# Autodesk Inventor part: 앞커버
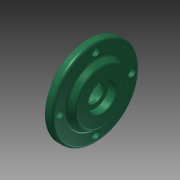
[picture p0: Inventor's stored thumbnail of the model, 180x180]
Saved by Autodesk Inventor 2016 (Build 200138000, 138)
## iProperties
Created: 2015-11
Part Number: 앞커버
Material: 알루미늄 6061
Document SubType Name: Modeling
Designer: mduedu
Density: 2.71 g/cm^3
Appearance: 매끄러움 - 짙은 바다 녹색
Mass: 245.264 g
Surface Area: 216.158 cm^2
Volume: 90.5034 cm^3
Author: mduedu
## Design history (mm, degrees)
sketch "스케치1"
  geometry: C1 r 47.5 at (0, 0); 1 further point
  constraints: 1 centre point, 1 coincident
  dimensions: "d57" = 95 diameter of C1
extrude "돌출1" new body sketch "스케치1" distance "d3" = 8; taper "d4" = 0 deg
sketch "스케치2"
  geometry: C1 r 32.5 at (0, 0); 1 further point
  constraints: 1 centre point, 1 coincident
  dimensions: "d5" = 65 diameter of C1
extrude "돌출2" join sketch "스케치2" distance "d6" = 7; taper "d7" = -30 deg
sketch "스케치3" dims "d58" = 78
  geometry: 3 further points
  constraints: 2 vertical alignment, 1 coincident, 2 other
hole "구멍1" sketch "스케치3" at (0, 39) diameter "d11" = 4.5; stored, may be unused: countersink angle "d15" = 90 deg, drill point angle "d17" = 118 deg; dims "d12" = 6, "d13" = 8, "d14" = 4.4, "d16" = 8
sketch "스케치4"
  geometry: C1 r 32.5 at (0, 0); 1 further point
  constraints: 1 centre point, 1 coincident
  dimensions: "d21" = 65 diameter of C1
extrude "돌출3" join sketch "스케치4" distance "d23" = 12; taper "d24" = 0 deg
hole "구멍2" diameter "d27" = 34; stored, may be unused: countersink angle "d31" = 90 deg, drill point angle "d33" = 0 deg; dims "d28" = 6, "d29" = 40, "d30" = 12, "d32" = 15, "d65" = 10, "d66" = 10
fillet "모깎기3" dims "d36" = 3
fillet "모깎기4" dims "d37" = 3
fillet "모깎기5" dims "d38" = 0.3
chamfer "모따기1" distance "d39" = 1; stored, may be unused: second distance "d40" = 2, angle "d41" = 45 deg
hole "구멍3" diameter "d44" = 20; stored, may be unused: countersink angle "d48" = 90 deg, drill point angle "d50" = 118 deg; dims "d45" = 6, "d46" = 30, "d47" = 8.3, "d49" = 8, "d59" = 10, "d60" = 10
fillet "모깎기6" dims "d51" = 0.3
chamfer "모따기2" distance "d52" = 0.8; stored, may be unused: second distance "d53" = 2, angle "d54" = 30 deg
node "솔리드1"
pattern_circular "원형 패턴1" dims angle "d19" = 360 deg
